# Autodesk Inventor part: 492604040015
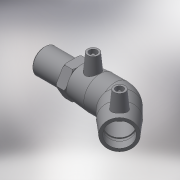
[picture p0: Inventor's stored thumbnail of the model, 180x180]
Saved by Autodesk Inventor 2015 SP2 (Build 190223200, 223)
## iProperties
Created: 2017-06
Part Number: 492604040015
Material: Generic
Description: PLASSON 45° ELBOW TRANSITION MALE 40-1.1/2"
Document SubType Name: Modeling
Designer: KIM
Mass: 201.396 g
Surface Area: 474.159 cm^2
Volume: 201.396 cm^3
Density: 1 g/cm^3
Appearance: Default
Author: KIM
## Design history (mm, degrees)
derived "492604.ipt"
feature "Solid1::492604.ipt"
tag "TaggingFeature1"
body "Solid1"
other parameters: "d2" = 56, "d4" = 27, "d5" = 50.4, "d8" = 168 deg, "d10" = 17.6, "d11" = 5.86667, "d29" = 47, "d30" = 15, "d31" = 37.8, "d34" = 5 deg, "d41" = 4, "d42" = 14, "d43" = 0, "d50" = 26, "d51" = 17.6, "d52" = 45.32, "d54" = 135 deg, "d86" = 25.2, "d87" = 135 deg, "d88" = 108, "d90" = 44, "d91" = 0, "d92" = 44, "d93" = 0, "d101" = 3, "d102" = 0, "d107" = 0.1, "d108" = 29, "d109" = 47.803, "d110" = 36, "d111" = 9, "d112" = 56, "d113" = 33.4621, "d114" = 32.4, "d116" = 1.68, "d122" = 0, "d123" = 2.39015, "L_" = 144, "L_1" = 44, "D_" = 29, "A_" = 47, "d_2" = 12, "L_2" = 36, "R_" = 47.803, "D_1" = 56
